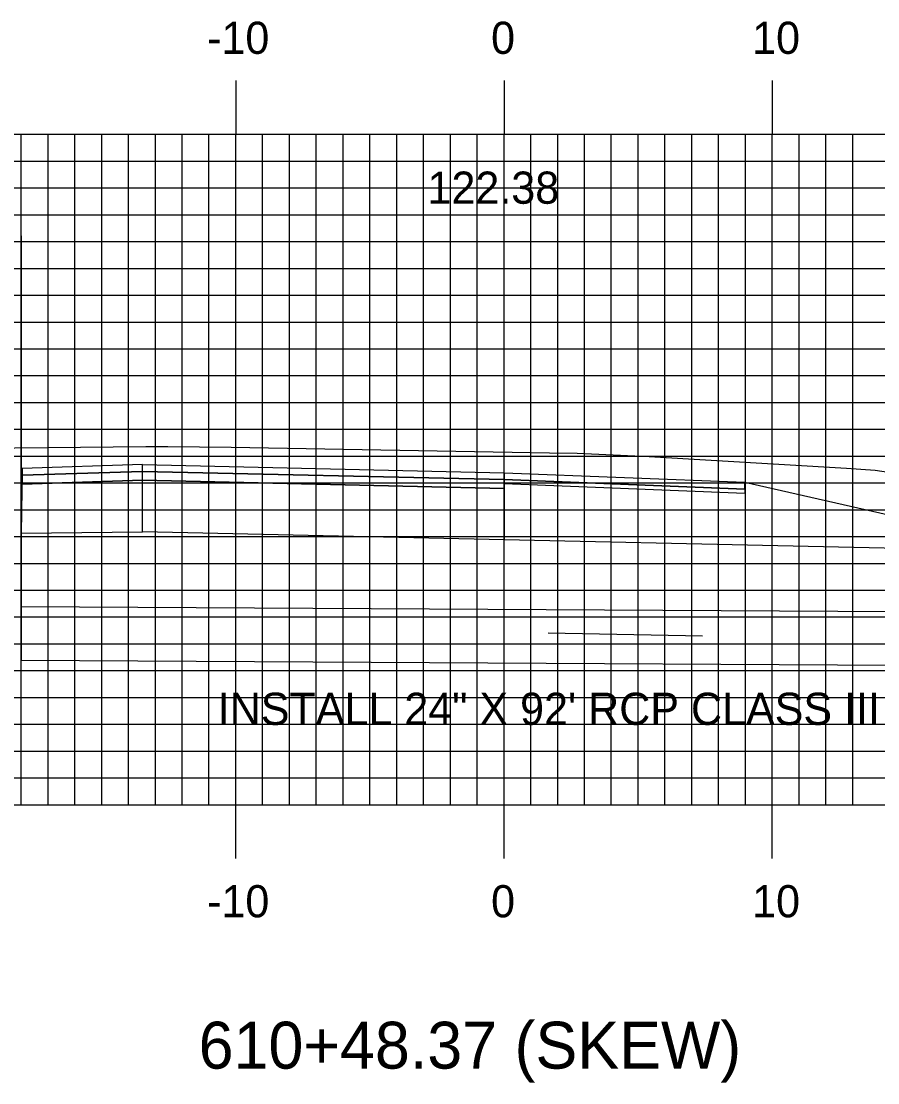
# Model space of a CAD drawing. Extents: x 843356 to 843699, y 363538 to 363758.
# Drawn here: x 843503.42 to 843535.36, y 363590.35 to 363629.94 of the extents above; entities that cross this region are included whole.
import ezdxf

# ---------------------------------------------------------------- set-up
doc = ezdxf.new("R2010")
doc.units = 0
for name, color, linetype in [('D_Drainage_Culvert', 7, 'Continuous'), ('D_Drainage_Text', 7, 'Continuous'), ('D_Roadway_Centerline_Text', 7, 'Continuous'), ('D_Roadway_Edge_Shoulder', 7, 'Continuous'), ('D_Roadway_Edge_TW', 7, 'Continuous'), ('D_Roadway_Pavement', 7, 'Continuous'), ('D_Roadway_SubGrade', 7, 'Continuous'), ('H_V ANNOTATION', 7, 'Continuous'), ('MAJOR', 7, 'Continuous'), ('MINOR', 7, 'Continuous'), ('S_Roadway_Centerline', 7, 'Continuous')]:
    doc.layers.add(name, color=color, linetype=linetype)

msp = doc.modelspace()

# ---------------------------------------------------------------- linework, layer by layer
at = {"layer": 'D_Drainage_Culvert'}
msp.add_line((843523.074, 363607.127), (843528.819, 363607.02), dxfattribs=at)
for points in [[(843503.424, 363608.108), (843551.264, 363607.833)], [(843503.424, 363606.108), (843551.252, 363605.833), (843551.264, 363607.833)]]:
    msp.add_lwpolyline(points, dxfattribs=at)
at = {"layer": 'D_Roadway_Edge_Shoulder'}
for points in [[(843507.949, 363613.402), (843503.457, 363613.262), (843503.457, 363613.012), (843507.949, 363613.152)], [(843521.424, 363613.102), (843530.408, 363612.743), (843530.408, 363612.493), (843521.424, 363612.852)]]:
    msp.add_lwpolyline(points, close=True, dxfattribs=at)
at = {"layer": 'D_Roadway_Edge_TW'}
msp.add_lwpolyline([(843507.949, 363613.402), (843521.424, 363613.102), (843521.424, 363612.852), (843507.949, 363613.152)], close=True, dxfattribs=at)
at = {"layer": 'D_Roadway_Pavement'}
for points in [[(843507.949, 363613.152), (843503.457, 363613.012), (843503.457, 363612.678), (843507.949, 363612.819)], [(843507.949, 363613.152), (843521.424, 363612.852), (843521.424, 363612.519), (843507.949, 363612.819)], [(843521.424, 363612.852), (843530.408, 363612.493), (843530.408, 363612.326), (843521.424, 363612.686)]]:
    msp.add_lwpolyline(points, close=True, dxfattribs=at)
msp.add_lwpolyline([(843521.424, 363612.852), (843521.424, 363612.519)], dxfattribs=at)
msp.add_lwpolyline([(843521.424, 363612.852), (843521.424, 363612.519)], dxfattribs=at)
at = {"layer": 'D_Roadway_SubGrade'}
msp.add_line((843503.424, 363621.939), (843503.424, 363606.108), dxfattribs=at)
for points in [[(843507.949, 363612.819), (843503.457, 363612.678), (843503.457, 363613.012), (843503.457, 363613.262), (843503.424, 363610.841), (843507.949, 363610.902)], [(843507.949, 363612.819), (843521.424, 363612.519), (843521.424, 363610.602), (843507.949, 363610.902)], [(843521.424, 363612.519), (843521.424, 363612.852), (843530.408, 363612.493), (843530.408, 363612.743), (843541.833, 363610.149), (843521.424, 363610.602)]]:
    msp.add_lwpolyline(points, close=True, dxfattribs=at)
at = {"layer": 'MAJOR'}
for p, q in [((843511.424, 363627.725), (843511.424, 363625.721)), ((843521.424, 363627.725), (843521.424, 363625.721)), ((843531.424, 363627.725), (843531.424, 363625.721)), ((843381.424, 363625.721), (843661.424, 363625.721)), ((843381.424, 363625.721), (843661.424, 363625.721)), ((843511.424, 363600.721), (843511.424, 363625.721)), ((843521.424, 363600.721), (843521.424, 363625.721)), ((843531.424, 363600.721), (843531.424, 363625.721)), ((843381.424, 363620.721), (843661.424, 363620.721)), ((843381.424, 363615.721), (843661.424, 363615.721)), ((843381.424, 363610.721), (843661.424, 363610.721)), ((843381.424, 363605.721), (843661.424, 363605.721)), ((843381.424, 363600.721), (843661.424, 363600.721)), ((843381.424, 363600.721), (843661.424, 363600.721)), ((843511.424, 363598.717), (843511.424, 363600.721)), ((843521.424, 363598.717), (843521.424, 363600.721)), ((843531.424, 363598.717), (843531.424, 363600.721))]:
    msp.add_line(p, q, dxfattribs=at)
at = {"layer": 'MINOR'}
for p, q in [((843503.424, 363600.721), (843503.424, 363625.721)), ((843504.424, 363600.721), (843504.424, 363625.721)), ((843505.424, 363600.721), (843505.424, 363625.721)), ((843506.424, 363600.721), (843506.424, 363625.721)), ((843507.424, 363600.721), (843507.424, 363625.721)), ((843508.424, 363600.721), (843508.424, 363625.721)), ((843509.424, 363600.721), (843509.424, 363625.721)), ((843510.424, 363600.721), (843510.424, 363625.721)), ((843512.424, 363600.721), (843512.424, 363625.721)), ((843513.424, 363600.721), (843513.424, 363625.721)), ((843514.424, 363600.721), (843514.424, 363625.721)), ((843515.424, 363600.721), (843515.424, 363625.721)), ((843516.424, 363600.721), (843516.424, 363625.721)), ((843517.424, 363600.721), (843517.424, 363625.721)), ((843518.424, 363600.721), (843518.424, 363625.721)), ((843519.424, 363600.721), (843519.424, 363625.721)), ((843520.424, 363600.721), (843520.424, 363625.721)), ((843522.424, 363600.721), (843522.424, 363625.721)), ((843523.424, 363600.721), (843523.424, 363625.721)), ((843524.424, 363600.721), (843524.424, 363625.721)), ((843525.424, 363600.721), (843525.424, 363625.721)), ((843526.424, 363600.721), (843526.424, 363625.721)), ((843527.424, 363600.721), (843527.424, 363625.721)), ((843528.424, 363600.721), (843528.424, 363625.721)), ((843529.424, 363600.721), (843529.424, 363625.721)), ((843530.424, 363600.721), (843530.424, 363625.721)), ((843532.424, 363600.721), (843532.424, 363625.721)), ((843533.424, 363600.721), (843533.424, 363625.721)), ((843534.424, 363600.721), (843534.424, 363625.721)), ((843381.424, 363624.721), (843661.424, 363624.721)), ((843381.424, 363623.721), (843661.424, 363623.721)), ((843381.424, 363622.721), (843661.424, 363622.721)), ((843381.424, 363621.721), (843661.424, 363621.721)), ((843381.424, 363619.721), (843661.424, 363619.721)), ((843381.424, 363618.721), (843661.424, 363618.721)), ((843381.424, 363617.721), (843661.424, 363617.721)), ((843381.424, 363616.721), (843661.424, 363616.721)), ((843381.424, 363614.721), (843661.424, 363614.721)), ((843381.424, 363613.721), (843661.424, 363613.721)), ((843381.424, 363612.721), (843661.424, 363612.721)), ((843381.424, 363611.721), (843661.424, 363611.721)), ((843381.424, 363609.721), (843661.424, 363609.721)), ((843381.424, 363608.721), (843661.424, 363608.721)), ((843381.424, 363607.721), (843661.424, 363607.721)), ((843381.424, 363606.721), (843661.424, 363606.721)), ((843381.424, 363604.721), (843661.424, 363604.721)), ((843381.424, 363603.721), (843661.424, 363603.721)), ((843381.424, 363602.721), (843661.424, 363602.721)), ((843381.424, 363601.721), (843661.424, 363601.721))]:
    msp.add_line(p, q, dxfattribs=at)
at = {"layer": 'S_Roadway_Centerline'}
msp.add_lwpolyline([(843500.734, 363614.006), (843508.07, 363614.076), (843508.892, 363614.076), (843511.252, 363614.056), (843523.119, 363613.849), (843524.157, 363613.834), (843526.837, 363613.71), (843534.194, 363613.277), (843535.257, 363613.198), (843539.3, 363612.586), (843543.743, 363612.01), (843549.991, 363611.121), (843560.013, 363606.776), (843562.204, 363606.204), (843563.96, 363605.815), (843572.238, 363605.857), (843572.92, 363605.839), (843577.258, 363605.822), (843579.697, 363606.524), (843587.369, 363609.026), (843594.753, 363612.067), (843599.661, 363613.294), (843607.961, 363615.829)], dxfattribs=at)

# ---------------------------------------------------------------- texts
at = {"layer": 'D_Drainage_Text'}
msp.add_text('INSTALL 24" X 92\' RCP CLASS III', height=1.2, dxfattribs=at).set_placement((843510.75, 363603.698))
at = {"layer": 'D_Roadway_Centerline_Text'}
msp.add_text('122.38', height=1.2, dxfattribs=at).set_placement((843518.572, 363623.132))
at = {"layer": 'H_V ANNOTATION'}
for s, height, p in [('-10', 1.2, (843510.354, 363628.721)), ('0', 1.2, (843520.942, 363628.721)), ('10', 1.2, (843530.675, 363628.721)), ('-10', 1.2, (843510.354, 363596.521)), ('0', 1.2, (843520.942, 363596.521)), ('10', 1.2, (843530.675, 363596.521)), ('610+48.37 (SKEW)', 1.74996, (843510.039, 363590.877))]:
    msp.add_text(s, height=height, dxfattribs=at).set_placement(p)

doc.saveas('drawing.dxf')
